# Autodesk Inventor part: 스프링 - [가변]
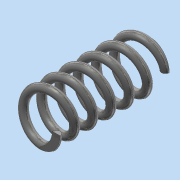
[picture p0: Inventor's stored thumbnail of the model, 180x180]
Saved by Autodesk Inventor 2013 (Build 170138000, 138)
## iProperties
Created: 2015-12
Part Number: 스프링 - [가변]
Material: 강철, 탄소
Document SubType Name: Modeling
Designer: Administrator
Density: 7.87 g/cm^3
Mass: -0.243265 g
Surface Area: 28.4714 cm^2
Volume: -0.0309104 cm^3
Author: Administrator
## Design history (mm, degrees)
sketch "스케치1"
  geometry: L1 (0, 0)-(0, 42); L2 (0, 42)-(8, 42); L3 (0, 0)-(8, 0); C1 r 1.5 at (8, 0)
  constraints: 6 end point, 1 centre point, 1 coincident, 1 parallel, 1 perpendicular, 1 vertical
  dimensions: "d0" = 42 distance of L1.start L1.end (derived); "d1" = 8 distance of L1.end L2.end; "d2" = 8 distance of L1.start L3.end; "d3" = 3 diameter of C1
feature "코일1" sketch "스케치1" pitch "d4" = 10; turns "d6" = 6; dims "d5" = 42 (= d0), "d7" = 0, angle "d8" = 90 deg, angle "d9" = 90 deg, "d10" = 0, "d11" = 0
sketch "스케치2"
  geometry: L1 (0, 10)-(42, 10); L2 (42, 10)-(42, -10); L3 (42, -10)-(0, -10); L4 (0, -10)-(0, 10); 2 further points
  constraints: 8 end point, 2 parallel, 1 coincident, 1 horizontal, 1 midpoint, 1 perpendicular
  dimensions: "d12" = 42 distance of L2.end L3.end (derived); "d14" = 20 distance of L1.end L2.end
extrude "돌출1" sketch "스케치2" stored distance "d15" = 10; taper "d16" = 0 deg
node "솔리드1"
